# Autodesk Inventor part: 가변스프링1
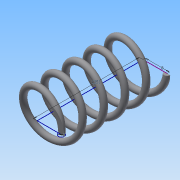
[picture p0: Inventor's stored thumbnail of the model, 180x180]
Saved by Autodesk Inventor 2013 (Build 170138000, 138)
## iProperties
Created: 2018-10
Part Number: 가변스프링1
Material: 일반
Document SubType Name: Modeling
Designer: Administrator
Density: 1 g/cm^3
Author: Administrator
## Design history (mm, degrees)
sketch "스케치1"
  geometry: L1 (0, 0)-(-8, 0); L2 (-8, 0)-(-8, 24.535); L3 (-8, 24.535)-(0, 24.535); C1 r 1 at (0, 0); 1 further point
  constraints: 6 end point, 1 centre point, 1 coincident, 1 horizontal, 1 parallel, 1 perpendicular, 1 vertical alignment
  dimensions: "d0" = 2 diameter of C1; "d2" = 24.53516 distance of L1.end L2.end (derived); "d3" = 8 distance of L2.end L3.end
feature "코일1" pitch "d4" = 10; turns "d6" = 5; dims "d5" = 24.53516 (= d2), "d7" = 0, angle "d8" = 90 deg, angle "d9" = 90 deg, "d10" = 0, "d11" = 0
sketch "스케치2"
  geometry: C1 r 22.863 at (0, 0); 1 further point
  constraints: 1 centre point, 1 coincident
extrude "돌출1" cut sketch "스케치2" distance "d12" = 10; taper "d13" = 0 deg
node "작업 평면1"
sketch "스케치3"
  geometry: C1 r 28.077 at (-8, 0); 1 further point
  constraints: 1 centre point, 1 coincident
extrude "돌출2" cut sketch "스케치3" distance "d14" = 10; taper "d15" = 0 deg
node "솔리드1"
